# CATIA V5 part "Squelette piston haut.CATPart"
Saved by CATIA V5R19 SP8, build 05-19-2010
Part number: Squelette piston haut
Publications: "Droite C (piston haut)", "Droite B (piston haut)", "Droite GH (piston haut)", "Droite CH (piston haut)", "Plan.5", "Plan.3", "Plan.1", "Plan.6", "Plan.7"
Bounding box of the stored display mesh (mm): x -62 to 12, y -104 to 76, z -50 to 50
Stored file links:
  G:\EU_thinkMotion\CFAO_2010\MMS_groupe3\MMS_groupe3\A reprendre\lpastor\lpastor\Squelette piston haut.CATPart
  C:\Users\Loïc\Documents\IFMA\Cours 2A\CFAO\Thinkmotion\Fourche avant.CATProduct
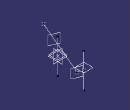
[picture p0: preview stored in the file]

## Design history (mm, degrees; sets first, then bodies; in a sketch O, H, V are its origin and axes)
Set1
  Point1 "C": linked copy from another document
  Point2 "B": linked copy from another document
  Point3 "G": linked copy from another document
  Point4 "H": linked copy from another document
Set2 "Set géométrique piston haut"
  Line1 "Droite C (piston haut)": type PtDir, RefPoint Point1, Direction xy-plane, Start -50, End 50
  Line2 "Droite B (piston haut)": type PtDir, RefPoint Point2, Direction xy-plane, Start -50, End 50
  Line3 "Droite GH (piston haut)": type PtPt, FirstPoint Point3, SecondPoint Point4
  Line4 "Droite CH (piston haut)": type PtPt, FirstPoint Point1, SecondPoint Point4
  Plane1: type Normal, Curve Line2, RefPoint Point2
  Plane2: type Offset, RefPlane Plane1, Offset 4
  Plane3: type Normal, Curve Line1, RefPoint Point1
  Plane4: type Offset, RefPlane Plane3, Offset 8
  Plane5: type Normal, Curve Line3, RefPoint Point4
  Plane6: type Offset, RefPlane Plane5, Offset -130
Body1 (main body)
